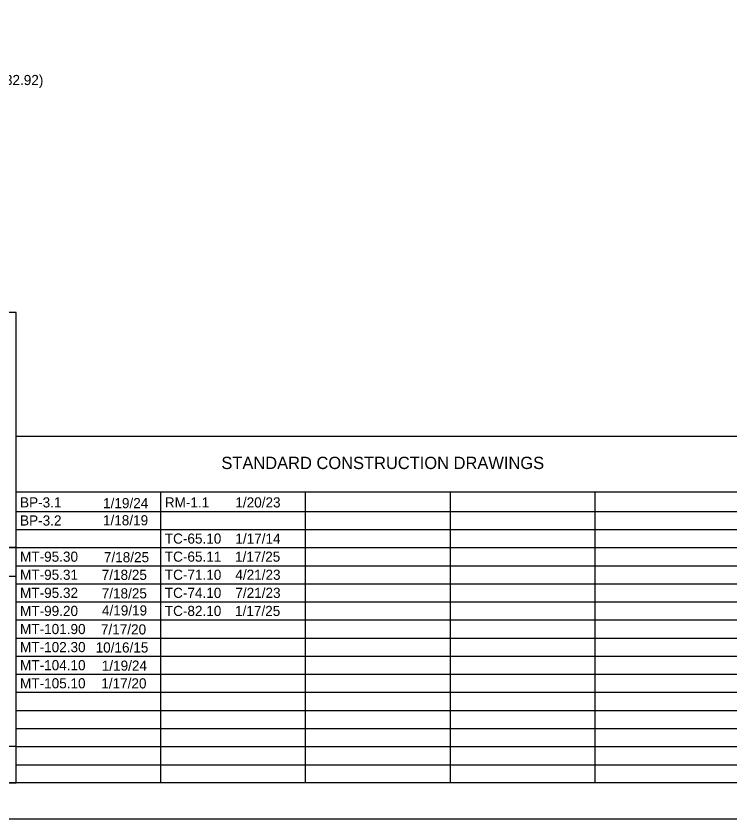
# Model space of a CAD drawing. Extents: x 0 to 34, y 0 to 22.
# Drawn here: x 10.15 to 20.01, y 0 to 11.1 of the extents above; entities that cross this region are included whole.
import ezdxf

# ---------------------------------------------------------------- set-up
doc = ezdxf.new("R2010")
doc.units = 0
for name, color, linetype in [('Default', 7, 'Continuous'), ('SH_Border', 7, 'Continuous'), ('SH_Cut_Line', 7, 'Continuous'), ('SH_Data', 7, 'Continuous'), ('SH_Text', 7, 'Continuous')]:
    doc.layers.add(name, color=color, linetype=linetype)

msp = doc.modelspace()

# ---------------------------------------------------------------- linework, layer by layer
at = {"layer": 'SH_Border'}
msp.add_lwpolyline([(1.5, 21.5), (33.5, 21.5), (33.5, 0.5), (1.5, 0.5)], close=True, dxfattribs=at)
at = {"layer": 'SH_Cut_Line'}
msp.add_lwpolyline([(0, 0), (34, 0), (34, 22), (0, 22)], close=True, dxfattribs=at)
at = {"layer": 'SH_Data'}
for p, q in [((10.15, 5.292), (23.6, 5.292)), ((10.15, 0.5), (10.15, 5.292)), ((10.15, 4.521), (23.6, 4.521)), ((12.15, 0.5), (12.15, 4.521)), ((14.15, 0.5), (14.15, 4.521)), ((16.15, 0.5), (16.15, 4.521)), ((18.15, 0.5), (18.15, 4.521)), ((10.15, 4.25), (23.6, 4.25)), ((10.15, 4), (23.6, 4)), ((10.15, 3.75), (7.35, 3.75)), ((10.15, 0.5), (10.15, 3.75)), ((10.15, 3.75), (23.6, 3.75)), ((10.15, 3.5), (23.6, 3.5)), ((10.15, 3.35), (7.35, 3.35)), ((10.15, 3.25), (23.6, 3.25)), ((10.15, 3), (23.6, 3)), ((10.15, 2.75), (23.6, 2.75)), ((10.15, 2.5), (23.6, 2.5)), ((10.15, 2.25), (23.6, 2.25)), ((10.15, 2), (23.6, 2)), ((10.15, 1.75), (23.6, 1.75)), ((10.15, 1.5), (23.6, 1.5)), ((10.15, 1.25), (23.6, 1.25)), ((10.15, 1), (23.6, 1)), ((10.15, 0.75), (23.6, 0.75)), ((10.15, 0.5), (7.35, 0.5))]:
    msp.add_line(p, q, dxfattribs=at)
for points in [[(10.15, 7), (7.35, 7), (7.35, 3.75), (10.15, 3.75)], [(10.15, 3.75), (7.35, 3.75), (7.35, 0.5), (10.15, 0.5)], [(10.15, 0.5), (10.15, 1), (7.35, 1), (7.35, 0.5)]]:
    msp.add_lwpolyline(points, close=True, dxfattribs=at)

# ---------------------------------------------------------------- texts
at = {"layer": 'Default'}
msp.add_text('(30.99 - 32.92)', height=0.14, dxfattribs=at).set_placement((9.299, 10.143))
at = {"layer": 'SH_Text'}
for s, height, p in [('STANDARD CONSTRUCTION DRAWINGS', 0.17, (12.986, 4.836)), ('BP-3.1', 0.14, (10.205, 4.305)), ('1/19/24', 0.14, (11.352, 4.295)), ('RM-1.1', 0.14, (12.205, 4.305)), ('1/20/23', 0.14, (13.179, 4.305)), ('BP-3.2', 0.14, (10.205, 4.055)), ('1/18/19', 0.14, (11.35, 4.058)), ('TC-65.10', 0.14, (12.205, 3.805)), ('1/17/14', 0.14, (13.179, 3.805)), ('MT-95.30', 0.14, (10.205, 3.555)), ('7/18/25', 0.14, (11.363, 3.548)), ('TC-65.11', 0.14, (12.205, 3.555)), ('1/17/25', 0.14, (13.175, 3.555)), ('MT-95.31', 0.14, (10.205, 3.305)), ('7/18/25', 0.14, (11.333, 3.304)), ('TC-71.10', 0.14, (12.205, 3.305)), ('4/21/23', 0.14, (13.179, 3.305)), ('MT-95.32', 0.14, (10.205, 3.055)), ('7/18/25', 0.14, (11.333, 3.048)), ('TC-74.10', 0.14, (12.205, 3.055)), ('7/21/23', 0.14, (13.179, 3.055)), ('MT-99.20', 0.14, (10.205, 2.805)), ('4/19/19', 0.14, (11.336, 2.812)), ('TC-82.10', 0.14, (12.205, 2.805)), ('1/17/25', 0.14, (13.175, 2.805)), ('MT-101.90', 0.14, (10.205, 2.555)), ('7/17/20', 0.14, (11.322, 2.55)), ('MT-102.30', 0.14, (10.205, 2.305)), ('10/16/15', 0.14, (11.249, 2.3)), ('MT-104.10', 0.14, (10.205, 2.055)), ('1/19/24', 0.14, (11.334, 2.049)), ('MT-105.10', 0.14, (10.205, 1.805)), ('1/17/20', 0.14, (11.327, 1.804))]:
    msp.add_text(s, height=height, dxfattribs=at).set_placement(p)

doc.saveas('drawing.dxf')
